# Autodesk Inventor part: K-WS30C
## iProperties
Created: 2009-07
Part Number: K-WS30C
Document SubType Name: Modeling
Designer: TB
Mass: 86.158 g
Surface Area: 195.043 cm^2
Volume: 86.158 cm^3
Density: 1 g/cm^3
Author: TB
